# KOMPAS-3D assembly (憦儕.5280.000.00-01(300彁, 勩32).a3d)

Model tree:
1. Плоскость XY
2. Плоскость ZX
3. Плоскость ZY
4. Ось X
5. Ось Y
6. Ось Z
7. Начало координат  (labels: Операция без истории:1; Операция без истории:2; Операция без истории:3; Импортированная поверхность:1)
8. Эскиз:1
9. Операция выдавливания:2
     Расстояние 1 = 4; Расстояние 2 = 10
10. Эскиз:2
11. Операция выдавливания:3
     Расстояние 1 = 4; Расстояние 2 = 10

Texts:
  133 1 134 1 135 1 136 0 50 1|SPDS|133 1 134 1 135 1 136 0 50 1
  125 1 126 1 127 1 128 0 50 1|SPDS|125 1 126 1 127 1 128 0 50 1
  129 1 130 1 131 1 132 0 50 1|SPDS|129 1 130 1 131 1 132 0 50 1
